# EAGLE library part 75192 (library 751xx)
75xxx DEVICE
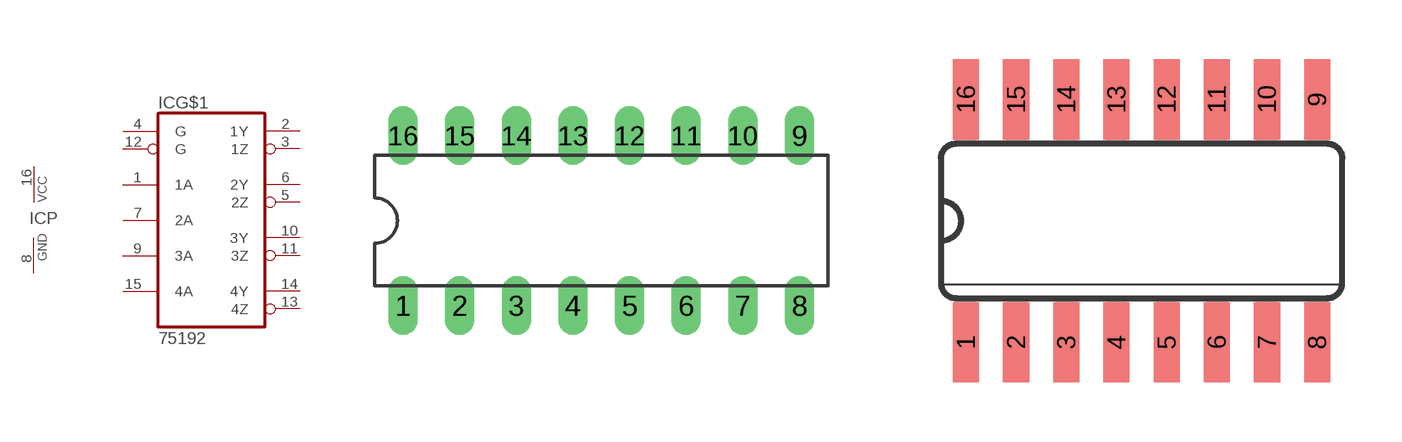
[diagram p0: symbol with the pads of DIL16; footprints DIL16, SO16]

Designator prefix IC; gates G$1=75192 P=PWRN

## 75192P  [DIL16]
1  G$1:1A  in
2  G$1:1Y  out
3  G$1:1Z  out
4  G$1:G  in
5  G$1:2Z  out
6  G$1:2Y  out
7  G$1:2A  in
8  P:GND  pwr
9  G$1:3A  in
10  G$1:3Y  out
11  G$1:3Z  out
12  G$1:G  in
13  G$1:4Z  out
14  G$1:4Y  out
15  G$1:4A  in
16  P:VCC  pwr

## 75192SO  [SO16]
Pads as for DIL16

## Footprint DIL16 (pad centres in mm)
Dual In Line Package
drill 0.813 long: 1 -8.89,-3.81; 2 -6.35,-3.81; 3 -3.81,-3.81; 4 -1.27,-3.81; 5 1.27,-3.81; 6 3.81,-3.81; 7 6.35,-3.81; 8 8.89,-3.81; 9 8.89,3.81; 10 6.35,3.81; 11 3.81,3.81; 12 1.27,3.81; 13 -1.27,3.81; 14 -3.81,3.81; 15 -6.35,3.81; 16 -8.89,3.81

## Footprint SO16 (pad centres in mm)
Small Outline package 150 mil
smd 0.66 x 2.032: 1 -4.445,-3.073; 2 -3.175,-3.073; 3 -1.905,-3.073; 4 -0.635,-3.073; 5 0.635,-3.073; 6 1.905,-3.073; 7 3.175,-3.073; 8 4.445,-3.073; 9 4.445,3.073; 10 3.175,3.073; 11 1.905,3.073; 12 0.635,3.073; 13 -0.635,3.073; 14 -1.905,3.073; 15 -3.175,3.073; 16 -4.445,3.073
